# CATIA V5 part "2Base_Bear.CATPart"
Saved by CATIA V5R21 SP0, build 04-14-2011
Part number: Base_Bear
Bounding box of the stored display mesh (mm): x 0 to 11, y -23.5 to 23.5, z -23.454 to 23.454
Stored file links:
  F:\教程\Robotic_Arm_Arduino_Kinect\机械臂CAD\Arm_Detailed_Design\Base_Bear.CATPart
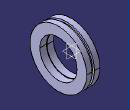
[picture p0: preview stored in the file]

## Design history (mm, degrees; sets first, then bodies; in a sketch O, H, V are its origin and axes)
Body1 (main body)
  Sketch1 on yz-plane, origin (0, 0, 0), H (0, 1, 0), V (0, 0, 1)
    circle A1 centre (0, 0) radius 23.5
    radius A1 = 23.5
  Pad1: profile Sketch1, direction (1, 0, 0), length 11
  Sketch2 on end face of Pad1, origin (11, 0, 0), H (0, 1, 0), V (0, 0, 1)
    circle A1 centre (0, 0) radius 15.5
    radius A1 = 15.5
  Pocket1: profile Sketch2, direction (-1, 0, 0), length 5.5
  Sketch3 on start face of Pad1, origin (0, 0, 0), H (0, -1, 0), V (0, 0, 1)
    circle A1 centre (0, 0) radius 15
    radius A1 = 15
  Pocket2: profile Sketch3, direction (1, 0, 0), length 5.5
  Sketch4 on xy-plane, origin (0, 0, 0), H (1, 0, 0), V (0, 1, 0)
    line L1 (4.5, 24.5625) -> (6.5, 24.5625)
    line L2 (6.5, 24.5625) -> (6.5, 22)
    line L3 (6.5, 22) -> (4.5, 22)
    line L4 (4.5, 22) -> (4.5, 24.5625)
    length L1 = 2
    distance V L4 = 4.5
    distance L3 H = 22
    horizontal: L1 H, L3 H
    vertical: L2 V, L4 V
  Groove1: profile Sketch4, axis axis of face of Pad1 from Sketch1.A1, angle 360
